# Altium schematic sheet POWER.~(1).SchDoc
size 431 x 279 mm; Date: Not shown in title block; ApprovedBy: Not shown in title block; CheckedBy: Not shown in title block; Author: Not shown in title block; CompanyName: Not shown in title block; DrawnBy: G. Fiolic; Engineer: Not shown in title block; Organization: Not shown in title block; Address1: Not shown in title block; Address2: Not shown in title block; Address3: Not shown in title block; Address4: Not shown in title block; DocumentNumber: 3; Revision: Use project parameter SCH_Rev; SheetNumber: 3; SheetTotal: 6; PageSetup: Record=PageOptions|CenterHorizontal=True|CenterVertical=True|PrintScale=1.00|XCorrection=1.00|YCorrection=1.00|PrintKind=0|BorderSize=5000000|LeftOffset=0|BottomOffset=0|Orientation=2|PaperLength=1000|PaperWidth=1000|Scale=100|PaperSource=15|PrintQuality=600|MediaType=1|DitherType=10|PaperKind=Letter|PrintScaleMode=1
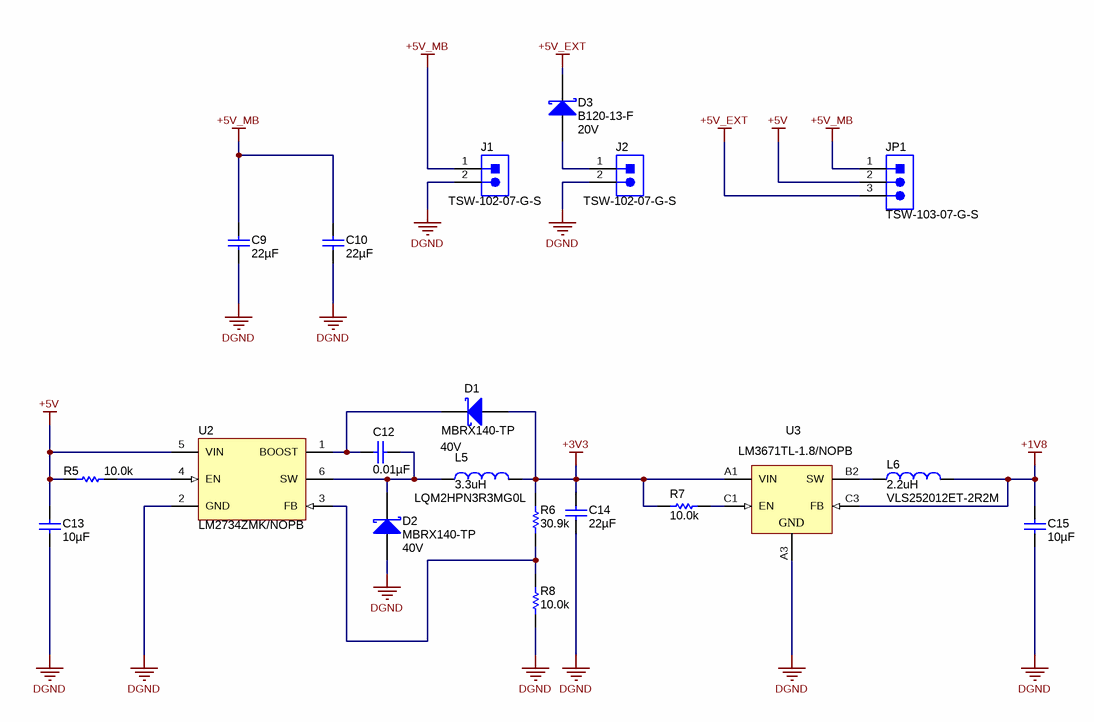
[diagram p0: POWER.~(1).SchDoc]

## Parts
C9  ValueDisplayed: 22µF  [0805]  (hidden comment: C2012X5R1C226K125AC)
C10  ValueDisplayed: 22µF  [0805]  (hidden comment: C2012X5R1C226K125AC)
C12  ValueDisplayed: 0.01µF  [0402L]  (hidden comment: GRM155R71H103KA88D)
C13  ValueDisplayed: 10µF  [1206L]  (hidden comment: GRM31CR71E106KA12L)
C14  ValueDisplayed: 22µF  [0805]  (hidden comment: C2012X5R1C226K125AC)
C15  ValueDisplayed: 10µF  [0805]  (hidden comment: GRM21BR70J106KE76L)
D1  MBRX140-TP  value 40V  [SOD-123]
D2  MBRX140-TP  value 40V  [SOD-123]
D3  B120-13-F  value 20V  [SMA]
J1  TSW-102-07-G-S  [TSW-102-07-G-S]
J2  TSW-102-07-G-S  [TSW-102-07-G-S]
JP1  TSW-103-07-G-S  [TSW-103-07-G-S]
L5  LQM2HPN3R3MG0L  value 3.3uH  [IND_1008]
L6  VLS252012ET-2R2M  value 2.2uH  [IND_1008]
R5  value 10.0k  [0402L]  (hidden comment: CRCW040210K0FKED)
R6  value 30.9k  [0402L]  (hidden comment: CRCW040230K9FKED)
R7  value 10.0k  [0402L]  (hidden comment: CRCW040210K0FKED)
R8  value 10.0k  [0402L]  (hidden comment: CRCW040210K0FKED)
U2  LM2734ZMK/NOPB  [MK06A_N]
U3  LM3671TL-1.8/NOPB  [TLA05CBA]

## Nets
+1V8: C15.1 L6.2 U3.C3(FB)
+3V3: C14.1 D1.2(A) L5.2 R6.1 R7.1 U3.A1(VIN)
+5V: C13.1 JP1.2 R5.1 U2.5(VIN)
+5V_EXT: D3.1(K) JP1.3
+5V_MB: C9.1 C10.1 J1.1 JP1.1
DGND: C9.2 C10.2 C13.2 C14.2 C15.2 D2.2(A) J1.2 J2.2 R8.2 U2.2(GND) U3.A3(GND)
NetC12_1: C12.1 D1.1(K) U2.1(BOOST)
NetC12_2: C12.2 D2.1(K) L5.1 U2.6(SW)
NetD3_2: D3.2(A) J2.1
NetL6_1: L6.1 U3.B2(SW)
NetR5_2: R5.2 U2.4(EN)
NetR6_2: R6.2 R8.1 U2.3(FB)
NetR7_2: R7.2 U3.C1(EN)

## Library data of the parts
C9 C10 C14 = C2012X5R1C226K125AC: CAP, CERM, 22uF, 16V, +/-10%, X5R, 0805; Manufacturer: TDK; Polarized: N; CompType: Capacitor; U/M: EA; Cap_F: 0.000022; Tolerance_%: 10; Value1: Unknown; VDC_V: 16; TaMin_C: -55; TaMax_C: 85
C12 = GRM155R71H103KA88D: CAP, CERM, 0.01uF, 50V, +/-10%, X7R, 0402; Manufacturer: MuRata; Polarized: N; CompType: Capacitor; U/M: EA; Cap_F: 0.00000001; Tolerance_%: 10; Value1: Unknown; VDC_V: 50; TaMin_C: -55; TaMax_C: 125; Cap_Case: 0402
C13 = GRM31CR71E106KA12L: CAP, CERM, 10uF, 25V, +/-10%, X7R, 1206; Manufacturer: MuRata; Polarized: N; CompType: Capacitor; U/M: EA; Cap_F: 0.00001; Tolerance_%: 10; Value1: Unknown; VDC_V: 25; TaMin_C: -55; TaMax_C: 125; Cap_Case: 2220
C15 = GRM21BR70J106KE76L: CAP, CERM, 10uF, 6.3V, +/-10%, X7R, 0805; Manufacturer: MuRata; Polarized: N; CompType: Capacitor; U/M: EA; Cap_F: 0.00001; Tolerance_%: 10; Value1: Unknown; VDC_V: 6.3; TaMin_C: -55; TaMax_C: 125
D1 D2 = Diode_Schottky: Diode, Schottky, 40V, 1A, SOD-123; Manufacturer: Micro Commercial Co; U/M: EA
D3 = B120-13-F: Diode, Schottky, 20V, 1A, SMA; Manufacturer: Diodes Inc.; U/M: EA; Vf_V: 0.5; Value2: 0.5V; Io_A: 1; Vr_V: 20; TJmax_C: 150
J1 J2 = TSW-102-07-G-S: Header, TH, 100mil, 2x1, Gold plated, 230 mil above insulator; Manufacturer: Samtec; SymbolCreator: a0412235; U/M: EA
JP1 = TSW-103-07-G-S: Header, TH, 100mil, 3x1, Gold plated, 230 mil above insulator; Manufacturer: Samtec; SymbolCreator: a0799628; U/M: EA
L5 = Inductor: Inductor, Shielded 3.3uH, 1200mA, 100 mohm, Surface Mount; Manufacturer: Murata Electronics North America; U/M: EA
L6 = Inductor: Inductor, SMT, Shielded Ferrite, 2.2uH, 1.75A, 154mohm; Manufacturer: TDK Corporation; U/M: EA
R5 R7 R8 = CRCW040210K0FKED: RES, 10.0k ohm, 1%, 0.063W, 0402; Manufacturer: Vishay-Dale; CompType: Resistor; Res_ohm: 10000; Value_Code: 10k0; Tolerance_%: 1; Power_W: 0.063; VDC_V: 50; TempCo: 100 ppm/C; EIA_Code: E96; U/M: EA
R6 = CRCW040230K9FKED: RES, 30.9k ohm, 1%, 0.063W, 0402; Manufacturer: Vishay-Dale; CompType: Resistor; Res_ohm: 30900; Value_Code: 30k9; Tolerance_%: 1; Power_W: 0.063; VDC_V: 50; TempCo: 100 ppm/C; EIA_Code: E96; U/M: EA
U2 = LM2734ZMK/NOPB: 1A Load Step-Down DC-DC Regulator, 6-pin Tiny SOT23, Pb-Free; Manufacturer: National Semiconductor; PackageTopMarking: SFTB*XTT; PowerWise: N; CompType: Switcher
U3 = LM3671TL-1.8/NOPB: 2MHz, 600mA Step-Down DC-DC Converter, 5-pin Micro SMD, Pb-Free; Manufacturer: National Semiconductor; PackageTopMarking: XV*I B; PowerWise: Y; CompType: MiscPower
